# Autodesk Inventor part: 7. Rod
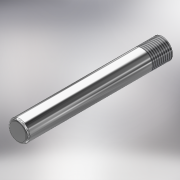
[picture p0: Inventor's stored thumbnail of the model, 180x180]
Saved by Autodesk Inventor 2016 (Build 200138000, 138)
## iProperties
Created: 2016-01
Part Number: 7. Rod
Material: Generic
Document SubType Name: Modeling
Designer: Black Falcon
Density: 1 g/cm^3
Appearance: Chrome - Polished
Author: Black Falcon
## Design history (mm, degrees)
sketch "Sketch1"
  geometry: C1 r 6.35 at (0, 0); 1 further point
  constraints: 1 centre point, 1 coincident
  dimensions: "d0" = 12.7 diameter of C1
extrude "Extrusion1" new body sketch "Sketch1" distance "d1" = 88.9; taper "d2" = 0 deg
thread "Thread1" dims "d5" = 12.7, "d6" = 0
fillet "Fillet1" dims "d7" = 1.27
body "Solid1"
